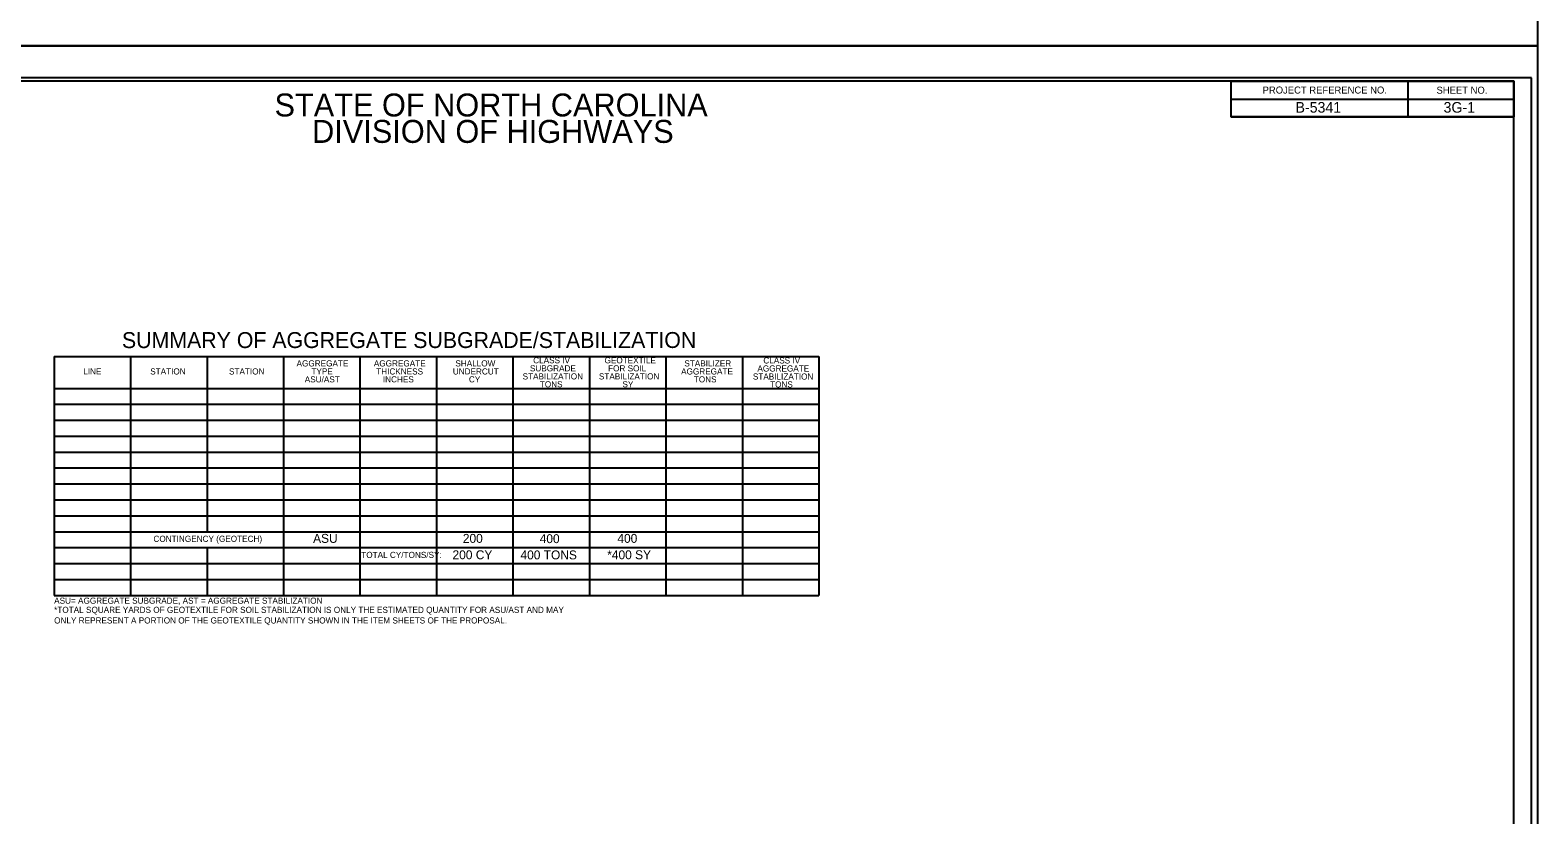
# Model space of a CAD drawing. Extents: x 1974126 to 1975810, y 438878 to 442173.
# Drawn here: x 1974742 to 1975810, y 439434 to 439990 of the extents above; entities that cross this region are included whole.
import ezdxf

# ---------------------------------------------------------------- set-up
doc = ezdxf.new("R2010")
doc.units = 0
for name, color, linetype in [('Prop Dimension Text', 7, 'Continuous'), ('Sheet Cutting Line CELL', 7, 'Continuous'), ('Sheet Data Field CELL', 7, 'Continuous'), ('Sheet Plot Border Inside CELL', 7, 'Continuous'), ('Sheet Plot Border Outside CELL', 7, 'Continuous'), ('Sheet Summary Combination CELL', 7, 'Continuous'), ('Sheet Summary Combination Grid CELL', 7, 'Continuous')]:
    doc.layers.add(name, color=color, linetype=linetype)

msp = doc.modelspace()

# ---------------------------------------------------------------- linework, layer by layer
at = {"layer": 'Sheet Cutting Line CELL'}
for p, q in [((1974125.6, 439978.3), (1975809.6, 439978.3)), ((1974125.6, 439978.3), (1975809.1, 439978.3)), ((1975809.6, 439978.3), (1974125.6, 439978.3))]:
    msp.add_line(p, q, dxfattribs=at)
at = {"layer": 'Sheet Plot Border Inside CELL'}
msp.add_lwpolyline([(1975805.1, 439955.8), (1974138.6, 439955.8), (1974138.6, 438900.7), (1975805.1, 438900.7)], close=True, dxfattribs=at)
at = {"layer": 'Sheet Plot Border Outside CELL'}
for points in [[(1975809.6, 441078.3), (1974125.6, 441078.3), (1974125.6, 439978.3), (1975809.6, 439978.3)], [(1975809.6, 439978.3), (1974125.6, 439978.3), (1974125.6, 438878.3), (1975809.6, 438878.3)]]:
    msp.add_lwpolyline(points, close=True, dxfattribs=at)
at = {"layer": 'Sheet Summary Combination CELL'}
for p, q in [((1975717.6, 439953.2), (1975717.6, 439928.2)), ((1975592.6, 439940.7), (1975792.6, 439940.7)), ((1975592.6, 439928.2), (1975792.6, 439928.2)), ((1974886.7, 439758.5), (1974886.7, 439758.5)), ((1974892.4, 439758.4), (1974892.4, 439758.4)), ((1974900.5, 439758.5), (1974900.5, 439758.5)), ((1974905.6, 439758.5), (1974905.6, 439758.5))]:
    msp.add_line(p, q, dxfattribs=at)
for points in [[(1975792.6, 439953.3), (1974292.6, 439953.3), (1974292.6, 438903.3), (1975792.6, 438903.3)], [(1975592.6, 439953.3), (1975792.6, 439953.3), (1975792.6, 439928.2), (1975592.6, 439928.2)]]:
    msp.add_lwpolyline(points, close=True, dxfattribs=at)
at = {"layer": 'Sheet Summary Combination Grid CELL'}
for p, q in [((1974759.3, 439758.5), (1975300.8, 439758.5)), ((1974759.3, 439758.5), (1974759.3, 439589.3)), ((1974813.4, 439758.5), (1974813.4, 439589.3)), ((1974867.6, 439758.5), (1974867.6, 439634.4)), ((1974921.7, 439758.5), (1974921.7, 439589.3)), ((1974975.9, 439758.5), (1974975.9, 439589.3)), ((1975030, 439758.5), (1975030, 439589.3)), ((1975084.2, 439758.5), (1975084.2, 439589.3)), ((1975138.3, 439758.5), (1975138.3, 439589.3)), ((1975192.5, 439758.5), (1975192.5, 439589.3)), ((1975246.6, 439758.5), (1975246.6, 439589.3)), ((1975300.8, 439758.5), (1975300.8, 439589.3)), ((1974759.3, 439735.9), (1975300.8, 439735.9)), ((1974759.3, 439724.7), (1975300.8, 439724.7)), ((1974759.3, 439713.4), (1975300.8, 439713.4)), ((1974759.3, 439702.1), (1975300.8, 439702.1)), ((1974759.3, 439690.8), (1975013.2, 439690.8)), ((1974759.3, 439690.8), (1975300.8, 439690.8)), ((1974759.3, 439679.5), (1975300.8, 439679.5)), ((1974759.3, 439668.2), (1975300.8, 439668.2)), ((1974759.3, 439657), (1975300.8, 439657)), ((1974759.3, 439645.7), (1975300.8, 439645.7)), ((1974759.3, 439634.4), (1975300.8, 439634.4)), ((1974759.3, 439623.1), (1975300.8, 439623.1)), ((1974867.6, 439623.1), (1974867.6, 439589.3)), ((1974759.3, 439611.8), (1975300.8, 439611.8)), ((1974759.3, 439600.6), (1975300.8, 439600.6)), ((1974759.3, 439589.3), (1975300.8, 439589.3))]:
    msp.add_line(p, q, dxfattribs=at)

# ---------------------------------------------------------------- texts
at = {"layer": 'Prop Dimension Text'}
for s, p in [('ASU', (1974942.7, 439626.5)), ('200', (1975048.7, 439626.5)), ('400', (1975103.1, 439626.3)), ('400', (1975158.1, 439626.5)), ('200 CY', (1975041.4, 439614.9)), ('400 TONS', (1975089.5, 439614.8)), ('*400 SY', (1975150.9, 439614.9))]:
    msp.add_text(s, height=6.32, dxfattribs=at).set_placement(p)
at = {"layer": 'Sheet Data Field CELL'}
for s, p in [('B-5341', (1975638.1, 439931.1)), ('3G-1', (1975742.9, 439931.1))]:
    msp.add_text(s, height=7.5, dxfattribs=at).set_placement(p)
at = {"layer": 'Sheet Summary Combination CELL'}
for s, height, p in [('STATE OF NORTH CAROLINA', 16.25, (1974915.4, 439928.4)), ('PROJECT REFERENCE NO.', 5, (1975614.8, 439944.6)), ('SHEET NO.', 5, (1975737.9, 439944.5)), ('DIVISION OF HIGHWAYS', 16.25, (1974942, 439909.7)), ('AGGREGATE', 4.33, (1974931, 439751.4)), ('LINE', 4.33, (1974780, 439745.7)), ('STATION', 4.33, (1974827.4, 439745.7)), ('STATION', 4.33, (1974883.2, 439745.7)), ('ASU/AST', 4.33, (1974936.8, 439740.1)), ('TYPE', 4.33, (1974941.5, 439745.7)), ('CONTINGENCY (GEOTECH)', 4.332, (1974829.7, 439627.2)), ('TOTAL CY/TONS/SY:', 4.332, (1974976.8, 439615.8)), ('ASU= AGGREGATE SUBGRADE, AST = AGGREGATE STABILIZATION', 4.332, (1974759.4, 439583.4)), ('*TOTAL SQUARE YARDS OF GEOTEXTILE FOR SOIL STABILIZATION IS ONLY THE ESTIMATED QUANTITY FOR ASU/AST AND MAY', 4.332, (1974759.4, 439576.9)), ('ONLY REPRESENT A PORTION OF THE GEOTEXTILE QUANTITY SHOWN IN THE ITEM SHEETS OF THE PROPOSAL.', 4.332, (1974759.4, 439569.4))]:
    msp.add_text(s, height=height, dxfattribs=at).set_placement(p)
msp.add_text('SUMMARY OF AGGREGATE SUBGRADE/STABILIZATION', height=11.281, rotation=0.0119, dxfattribs=at).set_placement((1974807.4, 439764.4))
at = {"layer": 'Sheet Summary Combination Grid CELL'}
for s, height, p in [('AGGREGATE', 4.33, (1974985.7, 439751.4)), ('SHALLOW', 4.33, (1975043.4, 439751.4)), ('SUBGRADE', 4.33, (1975096.2, 439747.9)), ('CLASS IV', 4.33, (1975098.5, 439753.6)), ('GEOTEXTILE', 4.33, (1975149, 439753.6)), ('FOR SOIL', 4.33, (1975151.5, 439747.9)), ('STABILIZER', 4.33, (1975205.5, 439751.4)), ('AGGREGATE', 4.33, (1975257.2, 439747.8)), ('CLASS IV', 4.33, (1975261.4, 439753.5)), ('THICKNESS', 4.33, (1974987.4, 439745.7)), ('INCHES', 4.33, (1974992.1, 439740.1)), ('UNDERCUT', 4.33, (1975041.6, 439745.7)), ('CY', 4.33, (1975053, 439740.1)), ('STABILIZATION', 4.332, (1975091, 439742.2)), ('TONS', 4.33, (1975103.2, 439736.6)), ('STABILIZATION', 4.332, (1975145, 439742.2)), ('SY', 4.33, (1975161.7, 439736.6)), ('AGGREGATE', 4.33, (1975203.2, 439745.7)), ('TONS', 4.33, (1975212.2, 439740.1)), ('STABILIZATION', 4.332, (1975254, 439742.1)), ('TONS', 4.33, (1975266.2, 439736.5))]:
    msp.add_text(s, height=height, dxfattribs=at).set_placement(p)

doc.saveas('drawing.dxf')
